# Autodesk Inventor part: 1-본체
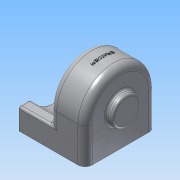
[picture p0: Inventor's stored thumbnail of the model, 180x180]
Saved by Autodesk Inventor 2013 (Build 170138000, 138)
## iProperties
Created: 2015-02
Part Number: 1-본체
Material: 알루미늄 6061
Document SubType Name: Modeling
Designer: Administrator
Density: 2.40731 g/cm^3
Mass: 511.244 g
Surface Area: 706.56 cm^2
Volume: 212.371 cm^3
Author: Administrator
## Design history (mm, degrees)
sketch "스케치1"
  geometry: L1 (0, 0)-(50, 0); L2 (50, 0)-(50, 100); L3 (50, 100)-(0, 100); L4 (0, 100)-(0, 0)
  constraints: 8 end point, 2 parallel, 1 horizontal, 1 perpendicular
  dimensions: "d0" = 50 distance of L2.end L3.end; "d2" = 100 distance of L1.end L2.end
extrude "돌출1" new body sketch "스케치1" distance "d3" = 100; taper "d4" = 0 deg
fillet "모깎기1" dims "d5" = 50
fillet "모깎기2" dims "d6" = 10
feature "쉘1" dims "d7" = 4
node "작업 평면2"
sketch "스케치5"
  geometry: L1 (-80, 0)-(0, 0) reference; L2 (-5.359, 30)-(10, 30); L3 (10, 30)-(10, 0); L4 (-90, 50)-(-90, 0) reference; L5 (-80, 0)-(-90, 0) reference; L6 (10, 0)-(0, 0) reference; L7 (-74.641, 30)-(-90, 30); A1 r 40 centre (-40, 50) between (-5.359, 30) and (-74.641, 30); 1 further point
  constraints: 6 end point, 2 parallel, 2 point on circle, 1 centre point, 1 collinear, 1 midpoint, 1 perpendicular, 1 point on line, 1 vertical alignment
  dimensions: "d16" = 40 radius of A1; "d19" = 50 distance from line of L1 A1.centre; "d20" = 30 distance between parallel lines of L6 L2
extrude "돌출3" join sketch "스케치5" stored distance "d21" = 49; taper "d22" = 0 deg
sketch "스케치6"
  geometry: C1 r 25 at (0, 0); A1 r 40 centre (0, 0) between (0, -40) and (0, 40) reference; 1 further point
  constraints: 1 centre point, 1 coincident
  dimensions: "d23" = 50 diameter of C1
extrude "돌출4" join sketch "스케치6" distance "d25" = 10; taper "d26" = -20 deg
sketch "스케치7"
  geometry: C1 r 20 at (0, 0); A1 r 40 centre (0, 0) between (0, 40) and (0, -40) reference; 1 further point
  constraints: 1 centre point, 1 coincident
  dimensions: "d27" = 40 diameter of C1
extrude "돌출5" join sketch "스케치7" distance "d29" = 9; taper "d30" = 0 deg
hole "구멍1" diameter "d33" = 20; stored, may be unused: countersink angle "d37" = 90 deg, drill point angle "d39" = 0 deg; dims "d31" = 10, "d32" = 10, "d34" = 6, "d35" = 28, "d36" = 10, "d38" = 14
hole "구멍2" diameter "d42" = 20; stored, may be unused: countersink angle "d46" = 90 deg, drill point angle "d48" = 0 deg; dims "d40" = 10, "d41" = 10, "d43" = 6, "d44" = 28, "d45" = 8, "d47" = 10
sketch "스케치8"
  geometry: C1 r 14 at (0, 0) reference; C2 r 21.36 at (0, 0) reference; A1 r 18 centre (0, 0) between (-18, 0) and (18, 0); 3 further points
  constraints: 4 point on circle, 2 horizontal alignment, 2 vertical alignment, 1 centre point, 1 coincident
  dimensions: "d49" = 36 diameter of A1
hole "구멍3" sketch "스케치8" at (-18, 0), (18, 0), (0, 18), (0, -18) diameter "d51" = 2.459; stored, may be unused: countersink angle "d55" = 90 deg, drill point angle "d57" = 118 deg; dims "d52" = 6, "d53" = 28, "d54" = 8, "d56" = 9
sketch "스케치9"
  geometry: L1 (45, 100)-(45, 0) reference; L2 (3, 91.75)-(36, 91.75); L3 (36, 91.75)-(36, 8.25); L4 (36, 8.25)-(3, 8.25); L5 (3, 8.25)-(3, 91.75); 7 further points
  constraints: 8 end point, 4 coincident, 2 midpoint, 2 parallel, 1 horizontal, 1 horizontal alignment, 1 perpendicular
  dimensions: "d58" = 33 distance of L2.start L2.end; "d60" = 83.5 distance of L2.end L3.end; "d61" = 9 distance between parallel lines of L3 L1
hole "구멍4" sketch "스케치9" at (3, 91.75), (36, 91.75), (3, 8.25), (36, 8.25) diameter "d62" = 5.134; stored, may be unused: countersink angle "d66" = 90 deg, drill point angle "d68" = 118 deg; dims "d63" = 10, "d64" = 28, "d65" = 8, "d67" = 13
chamfer "모따기1" distance "d69" = 1; stored, may be unused: second distance "d70" = 2, angle "d71" = 45 deg
fillet "모깎기3" dims "d72" = 3, "d73" = 0.3
node "작업 평면3"
sketch "스케치10"
  geometry: L1 (46.5, 17)-(46.5, -17) reference; L2 (37.5, 40)-(37.5, -40) reference; 3 further points
  constraints: 1 horizontal alignment, 1 midpoint, 1 other
  dimensions: "d76" = 25 distance from line of L2 point (12.5, 0)
feature "엠보싱1" sketch "스케치10" dims "d0" = 50, "d2" = 100, "d16" = 40, "d19" = 50, "d20" = 30, "d77" = 0.5, "d78" = 0
node "솔리드1"
other parameters: "d15" = -95
